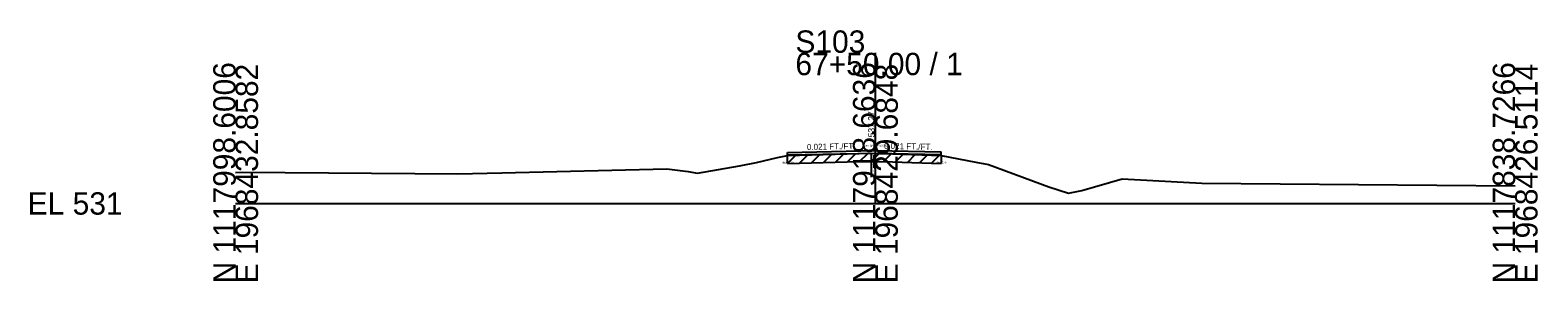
# Model space of a CAD drawing. Extents: x -26 to 163, y -10 to 24018.
# Drawn here: x -25.7 to 162.8, y 15490.3 to 15521.7 of the extents above; entities that cross this region are included whole.
import ezdxf

# ---------------------------------------------------------------- set-up
doc = ezdxf.new("R2010")
doc.units = 0
for name, color, linetype in [('RD_GPK_XS_Cell', 7, 'Continuous'), ('RD_XS_ExGround', 7, 'Continuous'), ('RD_XS_ExPaveRet', 7, 'Continuous'), ('RD_XS_Misc_Line', 7, 'Continuous'), ('RD_XS_PaveOvlay_CP', 7, 'Continuous'), ('RD_XS_TX_Elev_EX', 7, 'Continuous'), ('RD_XS_TX_ExEOP', 7, 'Continuous'), ('RD_XS_TX_Notes', 7, 'Continuous'), ('RD_XS_TX_Profile', 7, 'Continuous'), ('RD_XS_TX_Slope', 7, 'Continuous')]:
    doc.layers.add(name, color=color, linetype=linetype)

msp = doc.modelspace()

# ---------------------------------------------------------------- linework, layer by layer
at = {"layer": 'RD_GPK_XS_Cell'}
for p, q in [((80, 15500), (80, 15518.86)), ((0, 15500), (80, 15500)), ((80, 15500), (160, 15500))]:
    msp.add_line(p, q, dxfattribs=at)
at = {"layer": 'RD_XS_ExGround'}
msp.add_lwpolyline([(0, 15503.89), (0.81, 15503.9), (27.77, 15503.72), (33.3, 15503.85), (53.92, 15504.35), (56.59, 15503.99), (57.74, 15503.78), (63, 15504.72), (65.13, 15505.12), (67.77, 15505.74), (69.01, 15506), (76.47, 15506.21), (79.48, 15506.29), (80, 15506.27), (82.15, 15506.2), (88.24, 15506), (92.58, 15505.16), (94.14, 15504.87), (101.7, 15502.09), (104.13, 15501.28), (105.81, 15501.64), (110.87, 15503.09), (120.83, 15502.55), (160, 15502.22)], dxfattribs=at)
at = {"layer": 'RD_XS_ExPaveRet'}
for p, q in [((69.01, 15505), (70.04, 15506.03)), ((69.01, 15505), (69.01, 15506)), ((69.01, 15505), (76.47, 15505.21)), ((70.51, 15505.04), (71.54, 15506.07)), ((72.01, 15505.08), (73.04, 15506.11)), ((73.51, 15505.12), (74.54, 15506.15)), ((75.01, 15505.17), (76.04, 15506.2)), ((76.47, 15505.21), (79.48, 15505.29)), ((76.51, 15505.21), (77.54, 15506.24)), ((78.01, 15505.25), (79.04, 15506.27)), ((79.48, 15505.29), (80, 15505.27)), ((79.51, 15505.28), (80.48, 15506.25)), ((80, 15505.27), (82.15, 15505.2)), ((81.01, 15505.24), (81.98, 15506.2)), ((82.15, 15505.2), (88.24, 15505)), ((82.51, 15505.19), (83.48, 15506.16)), ((84.01, 15505.14), (84.98, 15506.11)), ((85.51, 15505.09), (86.48, 15506.06)), ((87.01, 15505.04), (87.98, 15506.01)), ((88.24, 15506), (88.24, 15505))]:
    msp.add_line(p, q, dxfattribs=at)
at = {"layer": 'RD_XS_Misc_Line'}
msp.add_line((79.48, 15506.29), (79.48, 15503.29), dxfattribs=at)
at = {"layer": 'RD_XS_PaveOvlay_CP'}
for p, q in [((69.01, 15506.39), (80, 15506.62)), ((69.01, 15506), (69.01, 15506.39)), ((80, 15506.27), (69.01, 15506.04)), ((80, 15506.62), (88.24, 15506.45)), ((88.24, 15506.1), (80, 15506.27)), ((88.24, 15506), (88.24, 15506.45))]:
    msp.add_line(p, q, dxfattribs=at)

# ---------------------------------------------------------------- texts
at = {"layer": 'RD_GPK_XS_Cell'}
for s, p in [('S103', (70, 15518.86)), ('67+50.00 / 1', (70, 15516.06)), ('EL 531', (-26, 15498.6))]:
    msp.add_text(s, height=2.8, dxfattribs=at).set_placement(p)
for s, p in [('N 1117998.6006', (0, 15490)), ('E 1968432.8582', (2.8, 15490)), ('N 1117918.6636', (80, 15490)), ('E 1968429.6848', (82.8, 15490)), ('N 1117838.7266', (160, 15490)), ('E 1968426.5114', (162.8, 15490))]:
    msp.add_text(s, height=2.8, rotation=90, dxfattribs=at).set_placement(p)
at = {"layer": 'RD_XS_TX_Elev_EX'}
msp.add_text('537.27', height=0.8, rotation=90, dxfattribs=at).set_placement((79.9, 15508.27))
at = {"layer": 'RD_XS_TX_ExEOP'}
for s, p in [('EOP-L', (68.96, 15506.39)), ('EOP-R', (88.19, 15506.45))]:
    msp.add_text(s, height=0.1, rotation=270, dxfattribs=at).set_placement(p)
at = {"layer": 'RD_XS_TX_Notes'}
for s, p in [('Elev. @CL = 537.62', (78.47, 15507.12)), (' dE= 0.39', (68.3, 15505)), (' dE= 0.35', (79.29, 15505.27)), (' dE= 0.44', (87.52, 15505))]:
    msp.add_text(s, height=0.25, dxfattribs=at).set_placement(p)
msp.add_text(' Min. Distance @CP = -0.03', height=0.25, rotation=270, dxfattribs=at).set_placement((79.73, 15507.37))
at = {"layer": 'RD_XS_TX_Profile'}
msp.add_text('CL', height=0.25, dxfattribs=at).set_placement((79.77, 15506.62))
at = {"layer": 'RD_XS_TX_Slope'}
for rotation, p in [(1.1916, (71.45, 15506.69)), (358.8084, (81.07, 15506.84))]:
    msp.add_text('0.021 FT./FT.', height=0.75, rotation=rotation, dxfattribs=at).set_placement(p)

doc.saveas('drawing.dxf')
